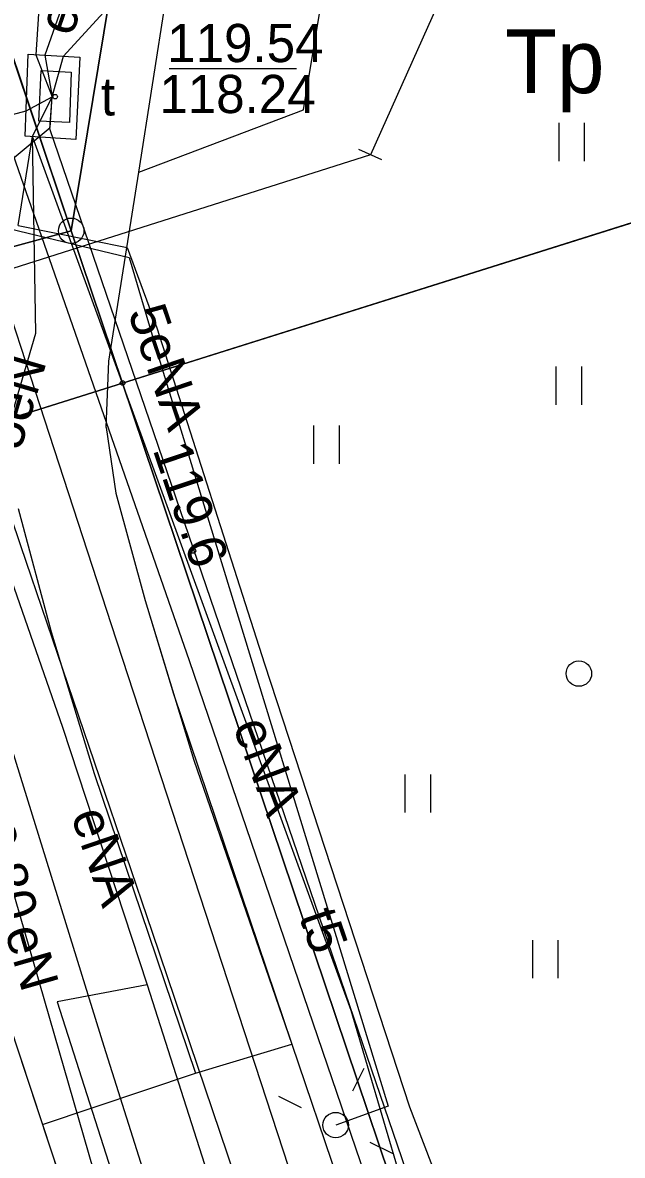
# Model space of a CAD drawing. Extents: x 6432121 to 6432331, y 5662538 to 5662686.
# Drawn here: x 6432265.79 to 6432277.55, y 5662627.61 to 5662649.83 of the extents above; entities that cross this region are included whole.
import ezdxf

# ---------------------------------------------------------------- set-up
doc = ezdxf.new("R2010")
doc.units = 0
for name, color, linetype in [('Warstwa 1', 7, 'Continuous'), ('Warstwa 10', 7, 'Continuous'), ('Warstwa 11', 7, 'Continuous'), ('Warstwa 12', 7, 'Continuous'), ('Warstwa 13', 7, 'Continuous'), ('Warstwa 14', 7, 'Continuous'), ('Warstwa 15', 7, 'Continuous'), ('Warstwa 2', 7, 'Continuous'), ('Warstwa 20', 7, 'Continuous'), ('Warstwa 4', 7, 'Continuous'), ('Warstwa 5', 7, 'Continuous'), ('Warstwa 6', 7, 'Continuous'), ('Warstwa 8', 7, 'Continuous'), ('Warstwa 9', 7, 'Continuous')]:
    doc.layers.add(name, color=color, linetype=linetype)

msp = doc.modelspace()

# ---------------------------------------------------------------- linework, layer by layer
at = {"layer": 'Warstwa 1'}
for p, q in [((6432266.742, 5662645.747), (6432268.232, 5662654.789)), ((6432266.742, 5662645.747), (6432268.232, 5662654.789)), ((6432263.798, 5662654.493), (6432266.742, 5662645.747)), ((6432263.798, 5662654.493), (6432266.742, 5662645.747)), ((6432267.75, 5662642.76), (6432279.29, 5662646.39)), ((6432267.75, 5662642.76), (6432279.29, 5662646.39)), ((6432245.39, 5662639.916), (6432266.742, 5662645.747)), ((6432245.39, 5662639.916), (6432266.742, 5662645.747)), ((6432266.742, 5662645.747), (6432267.75, 5662642.76)), ((6432266.742, 5662645.747), (6432267.75, 5662642.76)), ((6432246.69, 5662636.13), (6432267.75, 5662642.76)), ((6432246.69, 5662636.13), (6432267.75, 5662642.76)), ((6432267.75, 5662642.76), (6432287.64, 5662583.69)), ((6432267.75, 5662642.76), (6432287.64, 5662583.69))]:
    msp.add_line(p, q, dxfattribs=at)
at = {"layer": 'Warstwa 10'}
for points in [[(6432274.57, 5662659.22), (6432275.85, 5662656.39), (6432274.65, 5662651.8), (6432272.61, 5662647.24)], [(6432272.61, 5662647.24), (6432246.23, 5662638.85)]]:
    msp.add_lwpolyline(points, dxfattribs=at)
msp.add_circle((6432266.742, 5662645.747), 0.25, dxfattribs=at)
at = {"layer": 'Warstwa 11'}
msp.add_lwpolyline([(6432265.9, 5662649.21), (6432266.91, 5662649.15), (6432266.83, 5662647.54), (6432265.84, 5662647.6)], close=True, dxfattribs=at)
at = {"layer": 'Warstwa 12'}
for points in [[(6432245.267, 5662641.347), (6432245.28, 5662642.1), (6432247.25, 5662643.11), (6432265.86, 5662648.1), (6432266.37, 5662648.378), (6432266.59, 5662649.17), (6432271.25, 5662654.27), (6432275.48, 5662659.44), (6432277.44, 5662662.33), (6432277.171, 5662662.956), (6432277.15, 5662663.67), (6432276.74, 5662675.57), (6432276.54, 5662676.118), (6432276.69, 5662676.8), (6432276.108, 5662681.053)], [(6432245.267, 5662641.347), (6432245.28, 5662642.1), (6432247.25, 5662643.11), (6432265.86, 5662648.1), (6432266.37, 5662648.378), (6432266.59, 5662649.17), (6432271.25, 5662654.27), (6432275.48, 5662659.44), (6432277.44, 5662662.33), (6432277.171, 5662662.956), (6432276.74, 5662675.57), (6432276.54, 5662676.118), (6432276.69, 5662676.8), (6432276.108, 5662681.053)], [(6432259.267, 5662681.053), (6432259.329, 5662671.143), (6432259.331, 5662662.919), (6432260.078, 5662660.682), (6432263.877, 5662649.208), (6432267.527, 5662638.022), (6432271.438, 5662626.054), (6432273.548, 5662619.652), (6432276.516, 5662610.473), (6432279.664, 5662600.926), (6432282.613, 5662591.736), (6432284.976, 5662585.268), (6432286.395, 5662580.459), (6432288.268, 5662574.665)], [(6432288.269, 5662573.47), (6432290.18, 5662576.365), (6432289.651, 5662577.89), (6432283.657, 5662595.089), (6432278.636, 5662609.529), (6432275.228, 5662619.384), (6432273.259, 5662625.008), (6432269.06, 5662637.307), (6432265.455, 5662647.676), (6432262.131, 5662657.28), (6432261.494, 5662659.216), (6432262.228, 5662660.626), (6432262.598, 5662661.472), (6432263.21, 5662662.431), (6432263.592, 5662662.793), (6432265.636, 5662665.038), (6432264.282, 5662671.637), (6432263.631, 5662675.181), (6432263.032, 5662678.117), (6432262.911, 5662681.053)], [(6432258.356, 5662662.998), (6432258.39, 5662658.398), (6432260.508, 5662651.738), (6432262.768, 5662644.481), (6432265.197, 5662636.781), (6432267.384, 5662629.75), (6432269.748, 5662622.257), (6432272.462, 5662613.493), (6432273.441, 5662610.386), (6432276.081, 5662601.737), (6432278.642, 5662593.628), (6432281.263, 5662585.188), (6432283.543, 5662577.76), (6432283.852, 5662577.022), (6432284.284, 5662575.255)], [(6432261.338, 5662662.021), (6432260.831, 5662661.256), (6432261.33, 5662655.003), (6432261.566, 5662651.833), (6432262.397, 5662649.473), (6432263.18, 5662647.177), (6432265.745, 5662639.575), (6432268.331, 5662631.988), (6432271.28, 5662623.264), (6432274.385, 5662614.242), (6432277.778, 5662604.216), (6432280.796, 5662595.387), (6432284.518, 5662584.444), (6432287.071, 5662576.95), (6432288.269, 5662573.47)], [(6432274.57, 5662659.22), (6432275.85, 5662656.39), (6432274.65, 5662651.8), (6432272.61, 5662647.24)], [(6432268.316, 5662655.442), (6432268.305, 5662655.098), (6432266.226, 5662649.191), (6432266.37, 5662648.378)], [(6432266.378, 5662652.852), (6432266.196, 5662651.513), (6432266.047, 5662649.201), (6432266.37, 5662648.378)], [(6432262, 5662644.17), (6432266.33, 5662647.77), (6432266.37, 5662648.378)], [(6432264.48, 5662636.66), (6432264.52, 5662636.99), (6432264.81, 5662639.54), (6432266.05, 5662643.74), (6432265.984, 5662647.596), (6432266.37, 5662648.378)], [(6432265.703, 5662645.849), (6432265.984, 5662647.596), (6432266.37, 5662648.378)], [(6432294.644, 5662569.974), (6432292.199, 5662571.213), (6432291.73, 5662571.359), (6432291.554, 5662571.691), (6432290.843, 5662575.72), (6432287.011, 5662587.057), (6432285.41, 5662591.097), (6432281.352, 5662603.627), (6432279.346, 5662609.722), (6432279.211, 5662610.184), (6432279.026, 5662610.616), (6432274.158, 5662623.936), (6432272.237, 5662630.449), (6432265.984, 5662647.596), (6432266.37, 5662648.378)], [(6432291.73, 5662571.359), (6432291.68, 5662571.75), (6432289.74, 5662579), (6432288.94, 5662582.19), (6432279.33, 5662609.79), (6432279.211, 5662610.184), (6432278.94, 5662610.85), (6432266.32, 5662647.75), (6432266.37, 5662648.378)], [(6432272.61, 5662647.24), (6432246.23, 5662638.85)], [(6432264.97, 5662645.92), (6432267.88, 5662645.22), (6432268.52, 5662643.06), (6432272.96, 5662628.57), (6432271.93, 5662628.2)], [(6432265.703, 5662645.849), (6432267.84, 5662645.422), (6432268.419, 5662643.844), (6432270.537, 5662637.253), (6432273.378, 5662628.56)], [(6432265.301, 5662639.638), (6432266.569, 5662636.005), (6432268.23, 5662630.953)], [(6432268.05, 5662624.31), (6432264.48, 5662636.66)], [(6432268.23, 5662630.953), (6432266.467, 5662630.62)], [(6432268.23, 5662630.953), (6432270.582, 5662623.607), (6432273.222, 5662615.395), (6432273.419, 5662614.713)], [(6432266.467, 5662630.62), (6432269.173, 5662622.164), (6432270.14, 5662619.109)], [(6432273.378, 5662628.56), (6432274.214, 5662626.373), (6432275.936, 5662621.592), (6432276.137, 5662621.121), (6432277.158, 5662615.29), (6432277.656, 5662613.21), (6432277.121, 5662611.091), (6432279.065, 5662604.892), (6432281.714, 5662603.797), (6432281.489, 5662600.828), (6432283.129, 5662594.282), (6432283.903, 5662591.502), (6432284.529, 5662588.89)]]:
    msp.add_lwpolyline(points, dxfattribs=at)
msp.add_circle((6432267.75, 5662642.76), 0.045, dxfattribs=at)
at = {"layer": 'Warstwa 13'}
msp.add_circle((6432269.14, 5662639.466), 0.045, dxfattribs=at)
at = {"layer": 'Warstwa 14'}
msp.add_line((6432268.667, 5662648.931), (6432271.164, 5662648.931), dxfattribs=at)
msp.add_circle((6432266.427, 5662648.378), 0.045, dxfattribs=at)
at = {"layer": 'Warstwa 2'}
for centre in [(6432276.701, 5662637.059), (6432271.93, 5662628.2)]:
    msp.add_circle(centre, 0.25, dxfattribs=at)
at = {"layer": 'Warstwa 20'}
msp.add_line((6432272.838, 5662647.138), (6432272.382, 5662647.342), dxfattribs=at)
msp.add_line((6432272.838, 5662647.138), (6432272.382, 5662647.342), dxfattribs=at)
at = {"layer": 'Warstwa 4'}
msp.add_lwpolyline([(6432266.15, 5662648.89), (6432266.74, 5662648.86), (6432266.71, 5662647.87), (6432266.11, 5662647.9)], close=True, dxfattribs=at)
for points in [[(6432272.266, 5662628.871), (6432272.49, 5662629.318)], [(6432271.259, 5662628.536), (6432270.812, 5662628.76)], [(6432272.601, 5662627.864), (6432273.048, 5662627.64)]]:
    msp.add_lwpolyline(points, dxfattribs=at)
msp.add_circle((6432271.93, 5662628.2), 0.25, dxfattribs=at)
at = {"layer": 'Warstwa 5'}
for p, q in [((6432271.3, 5662648.12), (6432272.03, 5662652.56)), ((6432268.07, 5662646.9), (6432271.3, 5662648.12)), ((6432276.314, 5662647.112), (6432276.314, 5662647.862)), ((6432276.814, 5662647.112), (6432276.814, 5662647.862)), ((6432267.48, 5662643.19), (6432268.07, 5662646.9)), ((6432267.43, 5662641.89), (6432267.48, 5662643.19)), ((6432276.256, 5662642.331), (6432276.256, 5662643.081)), ((6432276.756, 5662642.331), (6432276.756, 5662643.081)), ((6432267.43, 5662641.89), (6432267.62, 5662640.6)), ((6432271.503, 5662641.175), (6432271.503, 5662641.925)), ((6432272.003, 5662641.175), (6432272.003, 5662641.925)), ((6432267.62, 5662640.6), (6432268.19, 5662638.49)), ((6432268.19, 5662638.49), (6432268.75, 5662636.664)), ((6432268.75, 5662636.664), (6432271.072, 5662629.787)), ((6432273.295, 5662634.33), (6432273.295, 5662635.08)), ((6432273.795, 5662634.33), (6432273.795, 5662635.08)), ((6432275.795, 5662631.08), (6432275.795, 5662631.83)), ((6432276.295, 5662631.08), (6432276.295, 5662631.83)), ((6432271.072, 5662629.787), (6432281.622, 5662598.544))]:
    msp.add_line(p, q, dxfattribs=at)
at = {"layer": 'Warstwa 6'}
for points in [[(6432241.262, 5662681.053), (6432241.262, 5662679.658), (6432244.087, 5662648.722), (6432245.39, 5662639.916), (6432266.742, 5662645.747), (6432263.798, 5662654.493), (6432266.973, 5662662.325), (6432263.799, 5662681.053)], [(6432295.199, 5662556.053), (6432289.811, 5662577.223), (6432287.64, 5662583.69), (6432267.75, 5662642.76), (6432246.69, 5662636.13), (6432263.163, 5662588.197), (6432269.007, 5662560.534), (6432269.756, 5662556.053)], [(6432261.53, 5662642.45), (6432261.725, 5662641.888), (6432263.054, 5662637.661), (6432266.526, 5662627.159), (6432271.921, 5662611.052), (6432274.366, 5662604.334), (6432277.03, 5662595.697), (6432280.318, 5662586.138), (6432281.64, 5662582.902)]]:
    msp.add_lwpolyline(points, dxfattribs=at)
for points in [[(6432266.973, 5662662.325), (6432263.798, 5662654.493), (6432266.742, 5662645.747), (6432268.232, 5662654.789), (6432301.273, 5662669.629)], [(6432268.232, 5662654.789), (6432266.742, 5662645.747), (6432267.75, 5662642.76), (6432279.29, 5662646.39), (6432287.724, 5662661.523), (6432302.18, 5662664.8), (6432302.345, 5662664.846), (6432301.273, 5662669.629)], [(6432278.892, 5662645.679), (6432279.29, 5662646.39), (6432267.75, 5662642.76), (6432287.64, 5662583.69), (6432294.025, 5662578.332), (6432295.024, 5662576.599), (6432295.196, 5662575.127), (6432301.46, 5662572.69), (6432295.88, 5662579.43), (6432289.26, 5662614.9)], [(6432245.39, 5662639.916), (6432246.69, 5662636.13), (6432267.75, 5662642.76), (6432266.742, 5662645.747)]]:
    msp.add_lwpolyline(points, close=True, dxfattribs=at)
at = {"layer": 'Warstwa 8'}
for p, q in [((6432264.503, 5662633.279), (6432266.179, 5662628.209)), ((6432266.179, 5662628.209), (6432266.526, 5662627.159))]:
    msp.add_line(p, q, dxfattribs=at)
msp.add_lwpolyline([(6432245.28, 5662642.1), (6432247.25, 5662643.11), (6432265.86, 5662648.1)], dxfattribs=at)
at = {"layer": 'Warstwa 9'}
for p, q in [((6432268.07, 5662646.9), (6432269.04, 5662653.09)), ((6432268.07, 5662646.9), (6432269.04, 5662653.09)), ((6432271.3, 5662648.12), (6432272.03, 5662652.56)), ((6432268.07, 5662646.9), (6432271.3, 5662648.12)), ((6432267.48, 5662643.19), (6432268.07, 5662646.9)), ((6432267.43, 5662641.89), (6432267.48, 5662643.19)), ((6432267.43, 5662641.89), (6432267.62, 5662640.6)), ((6432267.62, 5662640.6), (6432268.19, 5662638.49)), ((6432265.7, 5662640.3), (6432266.35, 5662637.88)), ((6432265.7, 5662640.3), (6432266.35, 5662637.88)), ((6432268.19, 5662638.49), (6432269.15, 5662635.36)), ((6432266.35, 5662637.88), (6432267.19, 5662635.1)), ((6432266.35, 5662637.88), (6432267.19, 5662635.1)), ((6432269.15, 5662635.36), (6432271.072, 5662629.787)), ((6432267.19, 5662635.1), (6432269.18, 5662629.22)), ((6432267.19, 5662635.1), (6432269.18, 5662629.22)), ((6432264.503, 5662633.279), (6432266.179, 5662628.209)), ((6432269.18, 5662629.22), (6432271.072, 5662629.787)), ((6432269.18, 5662629.22), (6432271.072, 5662629.787)), ((6432271.072, 5662629.787), (6432281.622, 5662598.544)), ((6432266.179, 5662628.209), (6432269.18, 5662629.22)), ((6432266.179, 5662628.209), (6432269.18, 5662629.22)), ((6432266.179, 5662628.209), (6432266.526, 5662627.159))]:
    msp.add_line(p, q, dxfattribs=at)

# ---------------------------------------------------------------- texts
at = {"layer": 'Warstwa 13'}
for s, rotation, p in [('eNA', 71.3046, (6432266.756, 5662649.537)), ('5eNA', 288.7936, (6432267.849, 5662644.148)), ('5eN', 73.5506, (6432265.743, 5662641.412)), ('119.6', 288.5129, (6432268.338, 5662641.457)), ('eNA', 290.7302, (6432269.905, 5662636.028)), ('eNA', 288.891, (6432266.731, 5662634.28)), ('t5', 288.8796, (6432271.208, 5662632.299)), ('eN', 286.1237, (6432265.435, 5662632.006))]:
    msp.add_text(s, height=0.75, rotation=rotation, dxfattribs=at).set_placement(p)
at = {"layer": 'Warstwa 14'}
msp.add_text('118.24', height=0.75, dxfattribs=at).set_placement((6432268.47, 5662648.056))
msp.add_text('118.80', height=0.75, rotation=286.1237, dxfattribs=at).set_placement((6432264.542, 5662635.096))
at = {"layer": 'Warstwa 15'}
msp.add_text('119.54', height=0.75, dxfattribs=at).set_placement((6432268.625, 5662649.056))
at = {"layer": 'Warstwa 2'}
msp.add_text('Tp', height=1.25, dxfattribs=at).set_placement((6432275.252, 5662648.447))
at = {"layer": 'Warstwa 5'}
msp.add_text('t', height=0.75, dxfattribs=at).set_placement((6432267.324, 5662648.009))

doc.saveas('drawing.dxf')
